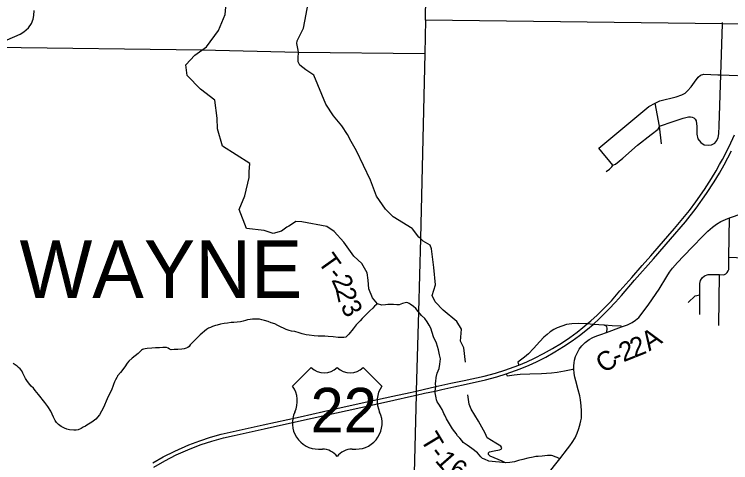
# Model space of a CAD drawing. Extents: x 2402298 to 2498138, y 789485 to 950881.
# Drawn here: x 2448638 to 2459820, y 864863 to 871864 of the extents above; entities that cross this region are included whole.
import ezdxf

# ---------------------------------------------------------------- set-up
doc = ezdxf.new("R2010")
doc.units = 0
for name, color, linetype in [('GM_X_County_Road', 7, 'Continuous'), ('GM_X_County_Road_Text', 7, 'Continuous'), ('GM_X_Interchange_Ramps', 7, 'Continuous'), ('GM_X_State_Route', 7, 'Continuous'), ('GM_X_Township', 7, 'Continuous'), ('GM_X_Township_Road', 7, 'Continuous'), ('GM_X_Township_Road_Text', 7, 'Continuous'), ('GM_X_Township_Text', 7, 'Continuous'), ('GM_X_US_Route', 7, 'Continuous'), ('GM_X_US_Shield', 7, 'Continuous')]:
    doc.layers.add(name, color=color, linetype=linetype)

msp = doc.modelspace()

# ---------------------------------------------------------------- linework, layer by layer
at = {"layer": 'GM_X_County_Road'}
for points in [[(2459800, 868685), (2459998, 868755), (2460135, 868805), (2460270, 868861)], [(2458118, 866983), (2458207, 867017), (2458281, 867051), (2458336, 867090), (2458384, 867130), (2458424, 867177), (2458540, 867336), (2458706, 867570), (2458823, 867771), (2458866, 867838), (2458911, 867901), (2458989, 867991), (2459083, 868089), (2459230, 868241), (2459382, 868397), (2459465, 868480), (2459536, 868543), (2459600, 868589), (2459664, 868627), (2459737, 868660), (2459800, 868685)], [(2457372, 866329), (2457371, 866375), (2457375, 866422), (2457382, 866462), (2457399, 866522), (2457422, 866575), (2457454, 866633), (2457494, 866685), (2457550, 866741), (2457613, 866787), (2457666, 866816), (2457730, 866842), (2457793, 866865), (2457884, 866898), (2458118, 866983)], [(2457153, 864924), (2457273, 865077), (2457311, 865128), (2457346, 865179), (2457390, 865252), (2457424, 865323), (2457452, 865399), (2457473, 865469), (2457483, 865515), (2457489, 865559), (2457493, 865615), (2457492, 865673), (2457488, 865751), (2457477, 865845), (2457465, 865905), (2457440, 866002), (2457404, 866139), (2457389, 866198), (2457378, 866256), (2457372, 866329)], [(2456728, 864386), (2456778, 864452), (2456948, 864667), (2457153, 864924)]]:
    msp.add_lwpolyline(points, dxfattribs=at)
at = {"layer": 'GM_X_Interchange_Ramps'}
for points in [[(2458118, 866983), (2458108, 866995), (2457972, 866999), (2457849, 867011), (2457672, 867022), (2457580, 867029), (2457443, 867038), (2457339, 867033), (2457257, 867019), (2457182, 866997), (2457112, 866970), (2457057, 866941), (2457004, 866906), (2456954, 866867), (2456905, 866822), (2456843, 866757), (2456741, 866645), (2456666, 866565), (2456604, 866511), (2456540, 866463), (2456495, 866434), (2456513, 866388)], [(2457884, 866898), (2457889, 866916), (2457894, 866944), (2457892, 866964), (2457886, 866982), (2457878, 866994), (2457866, 867003), (2457849, 867007), (2457849, 867011)], [(2456317, 866249), (2456329, 866219), (2456442, 866236), (2456532, 866245), (2456684, 866252), (2456869, 866257), (2457023, 866264), (2457114, 866275), (2457224, 866296), (2457355, 866324), (2457372, 866329)]]:
    msp.add_lwpolyline(points, dxfattribs=at)
at = {"layer": 'GM_X_State_Route'}
msp.add_lwpolyline([(2448492, 871450), (2448647, 871520), (2448728, 871553), (2448787, 871590), (2448857, 871654), (2448906, 871722), (2448930, 871789), (2448942, 871847), (2448946, 871925)], dxfattribs=at)
at = {"layer": 'GM_X_Township'}
msp.add_line((2455055, 871774), (2455047, 871253), dxfattribs=at)
for points in [[(2460401, 871709), (2459688, 871718), (2455055, 871774), (2455087, 873978), (2455132, 876575), (2455173, 879496), (2455207, 881924), (2455264, 885930), (2455318, 889770), (2455396, 895324), (2455493, 902184), (2455511, 903524), (2455798, 903521), (2455910, 903520), (2460796, 903505)], [(2436952, 871501), (2441170, 871455), (2443539, 871409), (2448340, 871349), (2451564, 871308), (2453075, 871274), (2455047, 871253), (2454976, 868366), (2454948, 867221), (2454912, 865985), (2454911, 865959), (2454910, 865921), (2454853, 863679), (2454854, 862987), (2454763, 859062), (2454590, 849912), (2454510, 846829), (2454470, 845007), (2454435, 843954)]]:
    msp.add_lwpolyline(points, dxfattribs=at)
at = {"layer": 'GM_X_Township_Road'}
for p, q in [((2459634, 867007), (2459643, 867799)), ((2459337, 867179), (2459338, 867483))]:
    msp.add_line(p, q, dxfattribs=at)
for points in [[(2453069, 871307), (2453049, 871410), (2453054, 871450), (2453151, 871650), (2453230, 872058), (2453239, 872138), (2453245, 872198), (2453260, 872228), (2453289, 872257), (2453377, 872307), (2453496, 872366), (2453631, 872437), (2453738, 872491), (2453885, 872628), (2454013, 872804), (2454255, 873117), (2454466, 873308), (2454594, 873454), (2454586, 873481), (2454537, 873636), (2454495, 873779), (2454475, 873841), (2454474, 873903)], [(2452305, 869383), (2452306, 869405), (2452313, 869536), (2451886, 869803), (2451810, 870076), (2451806, 870242), (2451770, 870525), (2451544, 870697), (2451337, 870909), (2451316, 871078), (2451457, 871228), (2451565, 871305), (2451636, 871356), (2451825, 871614), (2451930, 871861), (2451953, 872146), (2451855, 872432), (2451751, 872603)], [(2457877, 869411), (2457927, 869448), (2457963, 869483), (2457983, 869508), (2458020, 869526), (2458135, 869619), (2458366, 869820), (2458581, 869990), (2458686, 870073), (2458708, 870117), (2458924, 870189), (2459077, 870243), (2459162, 870263), (2459194, 870263), (2459218, 870257), (2459243, 870247), (2459265, 870229), (2459283, 870200), (2459290, 870112), (2459292, 869991), (2459305, 869921), (2459353, 869862), (2459406, 869827), (2459466, 869820), (2459518, 869825), (2459573, 869853), (2459603, 869896), (2459627, 869943), (2459637, 869997), (2459642, 870125), (2459667, 870918), (2459690, 871715), (2459690, 871739)], [(2454851, 868517), (2454848, 868521), (2454551, 868702), (2454433, 868822), (2454292, 869024), (2454200, 869275), (2453979, 869732), (2453894, 869881), (2453837, 869988), (2453750, 870122), (2453621, 870279), (2453503, 870463), (2453311, 870913), (2453187, 871000), (2453095, 871070), (2453068, 871121), (2453071, 871182), (2453076, 871272), (2453069, 871307)], [(2457764, 869775), (2458540, 870426), (2458643, 870479), (2458713, 870511), (2458971, 870574), (2459056, 870607), (2459107, 870633), (2459148, 870669), (2459205, 870733), (2459257, 870804), (2459314, 870884), (2459349, 870916), (2459400, 870928), (2459620, 870920)], [(2459620, 870920), (2459667, 870918), (2460193, 870899), (2460258, 870896), (2460444, 870889)], [(2458739, 869844), (2458708, 870117), (2458643, 870479)], [(2457983, 869508), (2457936, 869567), (2457809, 869717), (2457764, 869775)], [(2452569, 868480), (2452537, 868491), (2452261, 868518), (2452147, 868817), (2452237, 869032), (2452302, 869318), (2452305, 869383)], [(2454306, 867344), (2454231, 867437), (2454174, 867580), (2454161, 867713), (2454147, 867827), (2454060, 867973), (2453939, 868089), (2453782, 868304), (2453631, 868471), (2453516, 868550), (2453128, 868622), (2453033, 868628), (2452996, 868601), (2452922, 868556)], [(2459155, 867362), (2459264, 867470), (2459338, 867483), (2459338, 867662), (2459347, 867707), (2459377, 867750), (2459413, 867781), (2459468, 867802), (2459643, 867799), (2459715, 867798), (2459744, 867813), (2459767, 867833), (2459782, 867858), (2459790, 867879), (2459790, 868070), (2459800, 868685)], [(2452922, 868556), (2452892, 868539), (2452810, 868477), (2452676, 868443), (2452569, 868480)], [(2455681, 866433), (2455657, 866657), (2455601, 866762), (2455620, 866948), (2455545, 867067), (2455330, 867246), (2455208, 867376), (2455162, 867471), (2455212, 867642), (2455187, 867910), (2455149, 868204), (2455128, 868259), (2455019, 868324), (2454977, 868363), (2454952, 868387), (2454854, 868513), (2454851, 868517)], [(2459790, 868070), (2460033, 868062), (2460486, 868054), (2461321, 868036), (2461555, 868029)], [(2454942, 867226), (2454904, 867272), (2454869, 867301), (2454818, 867340), (2454799, 867351), (2454783, 867358), (2454763, 867363), (2454740, 867361), (2454696, 867350), (2454670, 867338), (2454643, 867328), (2454608, 867326), (2454555, 867331), (2454502, 867334), (2454469, 867332), (2454434, 867330), (2454375, 867324), (2454306, 867344)], [(2454306, 867344), (2454287, 867328), (2454261, 867308), (2454232, 867278), (2454185, 867234), (2454150, 867199), (2454109, 867155), (2454070, 867114), (2454037, 867079), (2454006, 867046), (2453976, 867013), (2453927, 866955), (2453861, 866871), (2453837, 866847), (2453824, 866835), (2453811, 866825), (2453782, 866816), (2453749, 866816), (2453693, 866820), (2453616, 866826), (2453538, 866832), (2453484, 866837), (2453441, 866838), (2453382, 866838), (2453316, 866845), (2453243, 866852), (2453192, 866859), (2453133, 866876), (2453086, 866890), (2453015, 866909), (2452967, 866919), (2452926, 866929), (2452882, 866943), (2452841, 866961), (2452801, 866980), (2452753, 867005), (2452703, 867029), (2452649, 867049), (2452598, 867068), (2452545, 867084), (2452503, 867094), (2452464, 867102), (2452427, 867103), (2452394, 867105), (2452357, 867103), (2452318, 867098), (2452279, 867091), (2452245, 867081), (2452210, 867071), (2452168, 867063), (2452119, 867059), (2452065, 867053), (2452022, 867050), (2451966, 867042), (2451913, 867035), (2451855, 867026), (2451804, 867012), (2451779, 867004), (2451733, 866990), (2451698, 866976), (2451670, 866963), (2451637, 866940), (2451605, 866916), (2451571, 866886), (2451539, 866857), (2451503, 866823), (2451470, 866794), (2451438, 866759), (2451406, 866725), (2451385, 866701), (2451365, 866678), (2451346, 866663), (2451321, 866650), (2451290, 866643), (2451252, 866637), (2451189, 866632), (2451132, 866628), (2451087, 866626), (2451061, 866634), (2451039, 866649), (2451011, 866660), (2450985, 866664), (2450954, 866662), (2450905, 866658), (2450841, 866654), (2450782, 866652), (2450712, 866645), (2450678, 866641), (2450655, 866635), (2450639, 866630), (2450623, 866620), (2450605, 866601), (2450571, 866570), (2450476, 866493), (2450426, 866447), (2450400, 866415), (2450364, 866362), (2450297, 866272), (2450253, 866223), (2450251, 866218)], [(2455212, 866102), (2455218, 866132), (2455225, 866195), (2455236, 866259), (2455270, 866335), (2455281, 866399), (2455291, 866484), (2455277, 866546), (2455258, 866626), (2455230, 866730), (2455183, 866829), (2455137, 866964), (2455116, 867012), (2455082, 867064), (2455045, 867113), (2454995, 867163), (2454949, 867218), (2454942, 867226)], [(2450251, 866218), (2450248, 866213), (2450238, 866193), (2450216, 866158), (2450201, 866125), (2450185, 866086), (2450178, 866054), (2450161, 866010), (2450089, 865862), (2450028, 865727), (2449966, 865611), (2449913, 865543), (2449846, 865496), (2449796, 865466), (2449770, 865450), (2449747, 865435), (2449714, 865416), (2449680, 865397), (2449633, 865376), (2449603, 865372), (2449567, 865370), (2449502, 865374), (2449457, 865385), (2449422, 865400), (2449367, 865429), (2449329, 865458), (2449295, 865488), (2449275, 865519), (2449248, 865575), (2449209, 865667), (2449163, 865742), (2449115, 865804), (2449013, 865928), (2448964, 865992), (2448935, 866027), (2448903, 866060), (2448881, 866082), (2448861, 866108), (2448836, 866146), (2448814, 866179), (2448794, 866221), (2448772, 866261), (2448754, 866295), (2448729, 866327), (2448705, 866351), (2448680, 866370), (2448652, 866390), (2448621, 866411)], [(2456307, 864863), (2456211, 864869), (2456149, 864874), (2456045, 864886), (2455976, 864917), (2455947, 864930), (2455919, 864954), (2455867, 865018), (2455780, 865086), (2455707, 865134), (2455646, 865179), (2455621, 865210), (2455590, 865245), (2455558, 865283), (2455534, 865316), (2455512, 865346), (2455480, 865391), (2455431, 865470), (2455384, 865547), (2455356, 865603), (2455344, 865631), (2455334, 865657), (2455314, 865694), (2455289, 865733), (2455276, 865763), (2455256, 865793), (2455241, 865814), (2455230, 865844), (2455222, 865874), (2455216, 865900), (2455210, 865925), (2455207, 865951), (2455205, 865981), (2455216, 866050), (2455212, 866097), (2455212, 866102)], [(2456307, 864863), (2456255, 864885), (2456127, 864940), (2456067, 864966), (2456038, 864988), (2456038, 865014), (2456057, 865034), (2456129, 865049), (2456211, 865064), (2456235, 865076), (2456248, 865096), (2456233, 865123), (2456154, 865165), (2456021, 865253), (2455988, 865325), (2455885, 865509), (2455768, 865699), (2455736, 865775), (2455719, 865922)], [(2457153, 864924), (2457113, 864943), (2457081, 864956), (2457046, 864969), (2457021, 864973), (2456995, 864974), (2456960, 864974), (2456919, 864972), (2456877, 864965), (2456816, 864961), (2456778, 864957), (2456736, 864947), (2456656, 864932), (2456578, 864914), (2456509, 864896), (2456445, 864878), (2456371, 864867), (2456307, 864863)], [(2456728, 864386), (2456778, 864452), (2456948, 864667), (2457153, 864924)]]:
    msp.add_lwpolyline(points, dxfattribs=at)
at = {"layer": 'GM_X_US_Route'}
for points in [[(2456513, 866388), (2456640, 866440), (2456756, 866493), (2456898, 866566), (2457039, 866645), (2457177, 866729), (2457308, 866818), (2457424, 866903), (2457514, 866972), (2457580, 867029), (2457639, 867079), (2457738, 867168), (2457876, 867305), (2457958, 867392), (2458091, 867544), (2458276, 867757), (2458440, 867944), (2458572, 868095), (2458702, 868245), (2458838, 868400), (2458944, 868521), (2459074, 868675), (2459175, 868802), (2459275, 868935), (2459411, 869131), (2459523, 869303), (2459591, 869419), (2459648, 869518), (2459690, 869595), (2459796, 869802), (2459880, 869985)], [(2456317, 866249), (2456536, 866329), (2456676, 866387), (2456791, 866440), (2456933, 866512), (2457075, 866592), (2457212, 866675), (2457344, 866765), (2457459, 866850), (2457584, 866948), (2457672, 867022), (2457774, 867115), (2457920, 867260), (2458023, 867371), (2458114, 867474), (2458321, 867712), (2458614, 868047), (2458879, 868351), (2459113, 868622), (2459280, 868835), (2459444, 869065), (2459560, 869246), (2459646, 869386), (2459718, 869514), (2459831, 869731)], [(2450800, 864859), (2450963, 864952), (2451142, 865043), (2451361, 865140), (2451533, 865205), (2451698, 865259), (2451868, 865306), (2452055, 865349), (2452522, 865454), (2453100, 865580), (2453646, 865702), (2454189, 865821), (2454547, 865901), (2454817, 865961), (2454913, 865982), (2455019, 866006), (2455216, 866050), (2455453, 866102), (2455662, 866148), (2455970, 866216), (2456147, 866262), (2456294, 866308), (2456513, 866388)], [(2455310, 866005), (2455496, 866046), (2455693, 866089), (2455993, 866157), (2456170, 866203), (2456317, 866249)], [(2450814, 864793), (2450987, 864893), (2451165, 864984), (2451384, 865081), (2451556, 865146), (2451721, 865200), (2451905, 865249), (2452069, 865287), (2452537, 865391), (2453123, 865521), (2453669, 865642), (2454212, 865762), (2454562, 865840), (2454840, 865902), (2454911, 865918), (2455042, 865947), (2455205, 865981), (2455310, 866005)]]:
    msp.add_lwpolyline(points, dxfattribs=at)
at = {"layer": 'GM_X_US_Shield'}
for p, q in [((2453272, 866350), (2452982, 866060)), ((2454374, 866060), (2454084, 866350)), ((2453388, 865074), (2453446, 865074)), ((2453910, 865074), (2453968, 865074))]:
    msp.add_line(p, q, dxfattribs=at)
for centre, radius, start, end in [((2453475, 866557), 290, 225.573, 314.427), ((2453881, 866557), 290, 225.573, 314.427), ((2452650, 865827), 406, 334.5471, 35.0009), ((2454707, 865827), 406, 144.9991, 205.4529), ((2453384, 865480), 406, 154.8319, 270.6383), ((2453973, 865480), 406, 269.3617, 25.1681), ((2453446, 864784), 290, 36.8699, 90), ((2453910, 864784), 290, 90, 143.1301)]:
    msp.add_arc(centre, radius, start, end, dxfattribs=at)

# ---------------------------------------------------------------- texts
at = {"layer": 'GM_X_County_Road_Text'}
for s, rotation, p in [('A', 33.3862, (2458549, 866598)), ('2', 21.8428, (2458319, 866499)), ('2', 21.6043, (2458146, 866430)), ('C', 36.8699, (2457853, 866247)), ('-', 21.8014, (2458032, 866384))]:
    msp.add_text(s, height=300, rotation=rotation, dxfattribs=at).set_placement(p)
at = {"layer": 'GM_X_Township_Road_Text'}
for s, rotation, p in [('T', 305.3972, (2453367, 867999)), ('-', 310.6841, (2453515, 867792)), ('2', 294.251, (2453584, 867718)), ('2', 282.649, (2453654, 867565)), ('3', 297.0976, (2453723, 867307)), ('T', 301.1074, (2454969, 865226)), ('-', 307.4318, (2455105, 865005)), ('1', 311.325, (2455193, 864891)), ('6', 330.4356, (2455399, 864685))]:
    msp.add_text(s, height=300, rotation=rotation, dxfattribs=at).set_placement(p)
at = {"layer": 'GM_X_Township_Text'}
msp.add_text('WAYNE', height=900, rotation=0, dxfattribs=at).set_placement((2448720, 867437))
at = {"layer": 'GM_X_US_Shield'}
msp.add_text('22', height=696.1, dxfattribs=at).set_placement((2453262, 865335))

doc.saveas('drawing.dxf')
